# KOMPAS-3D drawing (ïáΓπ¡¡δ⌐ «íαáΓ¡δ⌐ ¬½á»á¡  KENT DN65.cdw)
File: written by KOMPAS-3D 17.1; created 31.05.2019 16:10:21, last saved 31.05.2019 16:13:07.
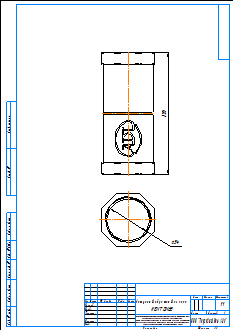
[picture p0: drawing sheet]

Sheet 1: A3, portrait

Title block, sheet 1: name: Латунный обратный клапан / KENT DN65; material: Внимание! Данный продукт является объектом авторского права ООО «Торговый Дом АДЛ». / Запрещается изменение, копирование, распространение / (в том числе путем копирования на другие сайты и ресурсы в Интернете) / или любое иное использование информации и объектов без предварительного / согласия правообладателя (ООО «Торговый Дом АДЛ»).; sheets: 1; organisation: ООО "Торговый дом АДЛ"; sheet format: A3

Views: Вид 1, Проекционный вид 2
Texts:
  user
Dimensions and other numbers on the sheet: 54; 155; 1:1; 1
